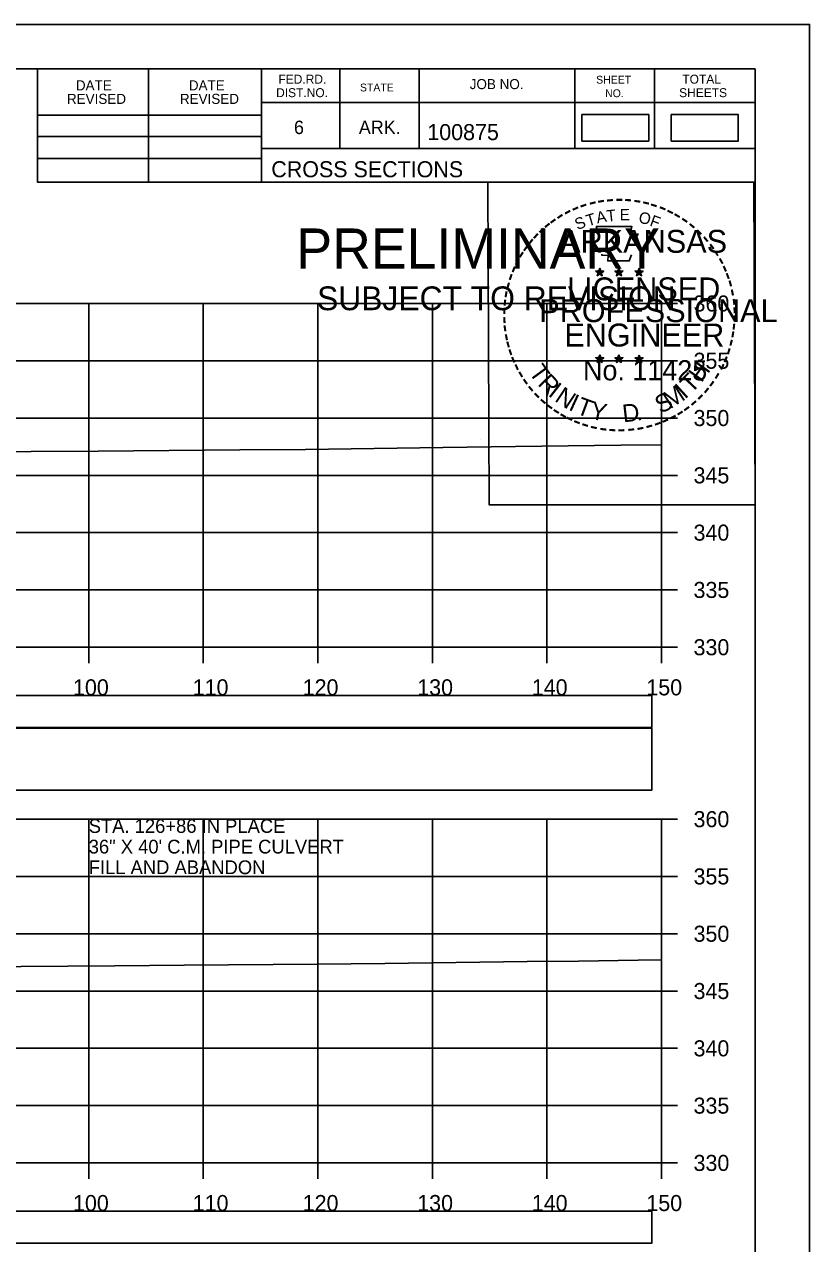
# Model space of a CAD drawing. Extents: x 1368122 to 1710785, y 373130 to 557566.
# Drawn here: x 1368783.3 to 1368851.8, y 376864 to 376970.4 of the extents above; entities that cross this region are included whole.
import ezdxf

# ---------------------------------------------------------------- set-up
doc = ezdxf.new("R2010")
doc.units = 0
for name, color, linetype in [('R_Alt Surface', 7, 'Continuous'), ('R_Axis', 7, 'Continuous'), ('R_Axis Annot', 7, 'Continuous'), ('R_Border', 7, 'Continuous'), ('R_Border PE', 7, 'Continuous'), ('R_Border Prem', 7, 'Continuous'), ('R_Drive', 7, 'Continuous'), ('R_Exist Surface', 7, 'Continuous'), ('R_Grid', 7, 'Continuous'), ('R_No Plot', 7, 'Continuous'), ('R_Water Annot', 7, 'Continuous')]:
    doc.layers.add(name, color=color, linetype=linetype)

msp = doc.modelspace()

# ---------------------------------------------------------------- linework, layer by layer
msp.add_lwpolyline([(1368539.73, 376903.58), (1368838.03, 376903.58), (1368838.03, 376908.99), (1368539.73, 376908.99)], close=True)
at = {"layer": 'R_Alt Surface'}
for points in [[(1368539.73, 376909.05), (1368838.03, 376909.05), (1368838.03, 376911.86), (1368539.73, 376911.86)], [(1368539.73, 376864.05), (1368838.03, 376864.05), (1368838.03, 376866.86), (1368539.73, 376866.86)]]:
    msp.add_lwpolyline(points, close=True, dxfattribs=at)
at = {"layer": 'R_Axis'}
for p, q in [((1368838.88, 376916.06), (1368838.88, 376946.06)), ((1368840.28, 376946.06), (1368838.88, 376946.06)), ((1368840.28, 376941.06), (1368838.88, 376941.06)), ((1368840.28, 376936.06), (1368838.88, 376936.06)), ((1368840.28, 376931.06), (1368838.88, 376931.06)), ((1368840.28, 376926.06), (1368838.88, 376926.06)), ((1368840.28, 376921.06), (1368838.88, 376921.06)), ((1368538.88, 376916.06), (1368838.88, 376916.06)), ((1368788.88, 376914.66), (1368788.88, 376916.06)), ((1368798.88, 376914.66), (1368798.88, 376916.06)), ((1368808.88, 376914.66), (1368808.88, 376916.06)), ((1368818.88, 376914.66), (1368818.88, 376916.06)), ((1368828.88, 376914.66), (1368828.88, 376916.06)), ((1368838.88, 376914.66), (1368838.88, 376916.06)), ((1368840.28, 376916.06), (1368838.88, 376916.06)), ((1368838.88, 376871.06), (1368838.88, 376901.06)), ((1368840.28, 376901.06), (1368838.88, 376901.06)), ((1368840.28, 376896.06), (1368838.88, 376896.06)), ((1368840.28, 376891.06), (1368838.88, 376891.06)), ((1368840.28, 376886.06), (1368838.88, 376886.06)), ((1368840.28, 376881.06), (1368838.88, 376881.06)), ((1368840.28, 376876.06), (1368838.88, 376876.06)), ((1368538.88, 376871.06), (1368838.88, 376871.06)), ((1368788.88, 376869.66), (1368788.88, 376871.06)), ((1368798.88, 376869.66), (1368798.88, 376871.06)), ((1368808.88, 376869.66), (1368808.88, 376871.06)), ((1368818.88, 376869.66), (1368818.88, 376871.06)), ((1368828.88, 376869.66), (1368828.88, 376871.06)), ((1368838.88, 376869.66), (1368838.88, 376871.06)), ((1368840.28, 376871.06), (1368838.88, 376871.06))]:
    msp.add_line(p, q, dxfattribs=at)
at = {"layer": 'R_Border'}
for p, q in [((1368530.88, 376966.52), (1368847.06, 376966.52)), ((1368784.42, 376956.64), (1368784.42, 376966.52)), ((1368794.1, 376956.64), (1368794.1, 376966.52)), ((1368803.96, 376966.52), (1368803.96, 376956.64)), ((1368810.8, 376966.52), (1368810.8, 376959.58)), ((1368817.74, 376966.52), (1368817.74, 376959.58)), ((1368831.32, 376966.52), (1368831.32, 376959.58)), ((1368838.26, 376966.52), (1368838.26, 376959.58)), ((1368847.06, 376761.06), (1368847.06, 376966.52)), ((1368847.06, 376963.58), (1368803.96, 376963.58)), ((1368847.06, 376963.6), (1368847.06, 376963.6)), ((1368784.42, 376962.5), (1368803.96, 376962.5)), ((1368784.42, 376960.64), (1368803.96, 376960.64)), ((1368847.06, 376959.58), (1368803.96, 376959.58)), ((1368806.92, 376959.58), (1368847.06, 376959.58)), ((1368784.42, 376958.7), (1368803.96, 376958.7)), ((1368847.06, 376956.64), (1368784.42, 376956.64))]:
    msp.add_line(p, q, dxfattribs=at)
at = {"layer": 'R_Border PE'}
for p, q in [((1368833.15, 376948.89), (1368833.49, 376948.78)), ((1368833.15, 376948.89), (1368833.4, 376948.85)), ((1368833.15, 376948.89), (1368833.38, 376948.77)), ((1368833.28, 376948.48), (1368833.49, 376948.78)), ((1368833.28, 376948.48), (1368833.4, 376948.73)), ((1368833.28, 376948.48), (1368833.49, 376948.7)), ((1368833.49, 376949.14), (1368833.45, 376948.89)), ((1368833.49, 376948.78), (1368833.49, 376949.14)), ((1368833.49, 376949.14), (1368833.54, 376948.89)), ((1368833.84, 376948.89), (1368833.49, 376948.78)), ((1368833.71, 376948.48), (1368833.49, 376948.78)), ((1368833.71, 376948.48), (1368833.49, 376948.7)), ((1368833.84, 376948.89), (1368833.56, 376948.84)), ((1368833.71, 376948.48), (1368833.57, 376948.77)), ((1368833.84, 376948.89), (1368833.64, 376948.79)), ((1368834.82, 376948.89), (1368835.16, 376948.78)), ((1368834.82, 376948.89), (1368835.07, 376948.85)), ((1368834.82, 376948.89), (1368835.05, 376948.77)), ((1368834.95, 376948.48), (1368835.16, 376948.78)), ((1368834.95, 376948.48), (1368835.07, 376948.73)), ((1368834.95, 376948.48), (1368835.16, 376948.7)), ((1368835.16, 376949.14), (1368835.12, 376948.89)), ((1368835.16, 376948.78), (1368835.16, 376949.14)), ((1368835.16, 376949.14), (1368835.21, 376948.89)), ((1368835.51, 376948.89), (1368835.16, 376948.78)), ((1368835.38, 376948.48), (1368835.16, 376948.78)), ((1368835.38, 376948.48), (1368835.16, 376948.7)), ((1368835.51, 376948.89), (1368835.23, 376948.84)), ((1368835.38, 376948.48), (1368835.24, 376948.77)), ((1368835.51, 376948.89), (1368835.31, 376948.79)), ((1368836.58, 376948.88), (1368836.93, 376948.77)), ((1368836.58, 376948.88), (1368836.83, 376948.83)), ((1368836.58, 376948.88), (1368836.82, 376948.76)), ((1368836.71, 376948.47), (1368836.93, 376948.77)), ((1368836.71, 376948.47), (1368836.84, 376948.71)), ((1368836.71, 376948.47), (1368836.93, 376948.69)), ((1368836.93, 376949.13), (1368836.89, 376948.88)), ((1368836.93, 376948.77), (1368836.93, 376949.13)), ((1368836.93, 376949.13), (1368836.98, 376948.88)), ((1368837.28, 376948.88), (1368836.93, 376948.77)), ((1368837.14, 376948.47), (1368836.93, 376948.77)), ((1368837.14, 376948.47), (1368836.93, 376948.68)), ((1368837.28, 376948.88), (1368836.99, 376948.83)), ((1368837.14, 376948.47), (1368837, 376948.76)), ((1368837.28, 376948.88), (1368837.07, 376948.78)), ((1368833.14, 376941.32), (1368833.49, 376941.21)), ((1368833.14, 376941.32), (1368833.39, 376941.27)), ((1368833.14, 376941.32), (1368833.38, 376941.2)), ((1368833.27, 376940.91), (1368833.49, 376941.21)), ((1368833.27, 376940.91), (1368833.4, 376941.15)), ((1368833.27, 376940.91), (1368833.49, 376941.13)), ((1368833.49, 376941.57), (1368833.45, 376941.32)), ((1368833.49, 376941.21), (1368833.49, 376941.57)), ((1368833.49, 376941.57), (1368833.54, 376941.32)), ((1368833.84, 376941.32), (1368833.49, 376941.21)), ((1368833.7, 376940.91), (1368833.49, 376941.21)), ((1368833.7, 376940.91), (1368833.49, 376941.12)), ((1368833.84, 376941.32), (1368833.55, 376941.27)), ((1368833.7, 376940.91), (1368833.57, 376941.2)), ((1368833.84, 376941.32), (1368833.63, 376941.22)), ((1368834.81, 376941.32), (1368835.16, 376941.21)), ((1368834.81, 376941.32), (1368835.06, 376941.27)), ((1368834.81, 376941.32), (1368835.05, 376941.2)), ((1368834.94, 376940.91), (1368835.16, 376941.21)), ((1368834.94, 376940.91), (1368835.07, 376941.15)), ((1368834.94, 376940.91), (1368835.16, 376941.13)), ((1368835.16, 376941.57), (1368835.12, 376941.32)), ((1368835.16, 376941.21), (1368835.16, 376941.57)), ((1368835.16, 376941.57), (1368835.21, 376941.32)), ((1368835.51, 376941.32), (1368835.16, 376941.21)), ((1368835.37, 376940.91), (1368835.16, 376941.21)), ((1368835.37, 376940.91), (1368835.16, 376941.12)), ((1368835.51, 376941.32), (1368835.22, 376941.27)), ((1368835.37, 376940.91), (1368835.24, 376941.2)), ((1368835.51, 376941.32), (1368835.3, 376941.22)), ((1368836.58, 376941.31), (1368836.93, 376941.2)), ((1368836.58, 376941.31), (1368836.83, 376941.26)), ((1368836.58, 376941.31), (1368836.81, 376941.19)), ((1368836.71, 376940.9), (1368836.93, 376941.2)), ((1368836.71, 376940.9), (1368836.84, 376941.14)), ((1368836.71, 376940.9), (1368836.92, 376941.12)), ((1368836.93, 376941.56), (1368836.89, 376941.31)), ((1368837.14, 376940.9), (1368836.92, 376941.11)), ((1368836.93, 376941.2), (1368836.93, 376941.56)), ((1368836.93, 376941.56), (1368836.98, 376941.31)), ((1368837.27, 376941.31), (1368836.93, 376941.2)), ((1368837.14, 376940.9), (1368836.93, 376941.2)), ((1368837.27, 376941.31), (1368836.99, 376941.26)), ((1368837.14, 376940.9), (1368837, 376941.19)), ((1368837.27, 376941.31), (1368837.07, 376941.21))]:
    msp.add_line(p, q, dxfattribs=at)
for points in [[(1368833.19, 376952.77), (1368833.46, 376951.94)], [(1368836.7, 376951.85), (1368836.84, 376952.13), (1368836.15, 376952.11), (1368836.3, 376952.77), (1368833.19, 376952.77)], [(1368833.68, 376950.35), (1368833.68, 376950.26), (1368834.24, 376950.24), (1368834.19, 376949.77), (1368836.06, 376949.77), (1368836.26, 376950.3)], [(1368833.49, 376949.14), (1368833.71, 376948.48), (1368833.15, 376948.89), (1368833.84, 376948.89), (1368833.28, 376948.48), (1368833.49, 376949.14)], [(1368835.16, 376949.14), (1368835.38, 376948.48), (1368834.82, 376948.89), (1368835.51, 376948.89), (1368834.95, 376948.48), (1368835.16, 376949.14)], [(1368836.93, 376949.13), (1368837.14, 376948.47), (1368836.58, 376948.88), (1368837.28, 376948.88), (1368836.71, 376948.47), (1368836.93, 376949.13)], [(1368833.49, 376941.57), (1368833.7, 376940.91), (1368833.14, 376941.32), (1368833.84, 376941.32), (1368833.27, 376940.91), (1368833.49, 376941.57)], [(1368835.16, 376941.57), (1368835.37, 376940.91), (1368834.81, 376941.32), (1368835.51, 376941.32), (1368834.94, 376940.91), (1368835.16, 376941.57)], [(1368836.93, 376941.56), (1368837.14, 376940.9), (1368836.58, 376941.31), (1368837.27, 376941.31), (1368836.71, 376940.9), (1368836.93, 376941.56)]]:
    msp.add_lwpolyline(points, dxfattribs=at)
for centre, radius in [((1368833.49, 376948.78), 0.172), ((1368833.49, 376948.78), 0.145), ((1368833.49, 376948.78), 0.116), ((1368833.49, 376948.78), 0.0991), ((1368833.49, 376948.78), 0.0747), ((1368833.49, 376948.78), 0.0495), ((1368833.49, 376948.78), 0.0296), ((1368835.16, 376948.78), 0.172), ((1368835.16, 376948.78), 0.145), ((1368835.16, 376948.78), 0.116), ((1368835.16, 376948.78), 0.0991), ((1368835.16, 376948.78), 0.0747), ((1368835.16, 376948.78), 0.0495), ((1368835.16, 376948.78), 0.0296), ((1368836.93, 376948.77), 0.172), ((1368836.93, 376948.77), 0.145), ((1368836.93, 376948.77), 0.116), ((1368836.93, 376948.77), 0.0991), ((1368836.93, 376948.77), 0.0747), ((1368836.93, 376948.77), 0.0495), ((1368836.93, 376948.77), 0.0296), ((1368833.49, 376941.21), 0.172), ((1368833.49, 376941.21), 0.145), ((1368833.49, 376941.21), 0.116), ((1368833.49, 376941.21), 0.0991), ((1368833.49, 376941.21), 0.0747), ((1368833.49, 376941.21), 0.0495), ((1368833.49, 376941.21), 0.0296), ((1368835.16, 376941.21), 0.172), ((1368835.16, 376941.21), 0.145), ((1368835.16, 376941.21), 0.116), ((1368835.16, 376941.21), 0.0991), ((1368835.16, 376941.21), 0.0747), ((1368835.16, 376941.21), 0.0495), ((1368835.16, 376941.21), 0.0296), ((1368836.93, 376941.2), 0.172), ((1368836.93, 376941.2), 0.145), ((1368836.93, 376941.2), 0.116), ((1368836.93, 376941.2), 0.0991), ((1368836.93, 376941.2), 0.0747), ((1368836.93, 376941.2), 0.0495), ((1368836.93, 376941.2), 0.0296)]:
    msp.add_circle(centre, radius, dxfattribs=at)
at = {"layer": 'R_Drive'}
for points in [[(1368831.93, 376960.23), (1368837.77, 376960.23), (1368837.77, 376962.54), (1368831.93, 376962.54)], [(1368839.74, 376960.23), (1368845.58, 376960.23), (1368845.58, 376962.54), (1368839.74, 376962.54)]]:
    msp.add_lwpolyline(points, close=True, dxfattribs=at)
at = {"layer": 'R_Exist Surface'}
for points in [[(1368729.58, 376932.49), (1368745.62, 376932.97), (1368749.59, 376932.96), (1368756.77, 376933.04), (1368771.96, 376933.08), (1368783.85, 376933.13), (1368789.71, 376933.18), (1368802.07, 376933.29), (1368807.81, 376933.32), (1368819.78, 376933.5), (1368826.13, 376933.58), (1368835.33, 376933.69), (1368838.88, 376933.73)], [(1368733.93, 376887.72), (1368745.81, 376888.08), (1368748.59, 376888.06), (1368752.7, 376888.08), (1368772.93, 376888.14), (1368778.86, 376888.17), (1368791.15, 376888.26), (1368797.21, 376888.31), (1368808.86, 376888.39), (1368814.72, 376888.47), (1368827.17, 376888.63), (1368831.64, 376888.68), (1368836.86, 376888.75), (1368838.88, 376888.78)]]:
    msp.add_lwpolyline(points, dxfattribs=at)
at = {"layer": 'R_Grid'}
for p, q in [((1368538.88, 376946.06), (1368838.88, 376946.06)), ((1368788.88, 376916.06), (1368788.88, 376946.06)), ((1368798.88, 376916.06), (1368798.88, 376946.06)), ((1368808.88, 376916.06), (1368808.88, 376946.06)), ((1368818.88, 376916.06), (1368818.88, 376946.06)), ((1368828.88, 376916.06), (1368828.88, 376946.06)), ((1368838.88, 376916.06), (1368838.88, 376946.06)), ((1368538.88, 376941.06), (1368838.88, 376941.06)), ((1368538.88, 376936.06), (1368838.88, 376936.06)), ((1368538.88, 376931.06), (1368838.88, 376931.06)), ((1368538.88, 376926.06), (1368838.88, 376926.06)), ((1368538.88, 376921.06), (1368838.88, 376921.06)), ((1368538.88, 376916.06), (1368838.88, 376916.06)), ((1368538.88, 376901.06), (1368838.88, 376901.06)), ((1368788.88, 376871.06), (1368788.88, 376901.06)), ((1368798.88, 376871.06), (1368798.88, 376901.06)), ((1368808.88, 376871.06), (1368808.88, 376901.06)), ((1368818.88, 376871.06), (1368818.88, 376901.06)), ((1368828.88, 376871.06), (1368828.88, 376901.06)), ((1368838.88, 376871.06), (1368838.88, 376901.06)), ((1368538.88, 376896.06), (1368838.88, 376896.06)), ((1368538.88, 376891.06), (1368838.88, 376891.06)), ((1368538.88, 376886.06), (1368838.88, 376886.06)), ((1368538.88, 376881.06), (1368838.88, 376881.06)), ((1368538.88, 376876.06), (1368838.88, 376876.06)), ((1368538.88, 376871.06), (1368838.88, 376871.06))]:
    msp.add_line(p, q, dxfattribs=at)
at = {"layer": 'R_No Plot'}
for p, q in [((1368518.48, 376970.41), (1368851.81, 376970.41)), ((1368823.09, 376934.18), (1368823.09, 376934.18))]:
    msp.add_line(p, q, dxfattribs=at)
for points in [[(1368518.47, 376970.41), (1368851.81, 376970.41), (1368851.81, 376757.07), (1368518.47, 376757.07)], [(1368764.8, 376966.52), (1368784.42, 376966.52), (1368784.42, 376956.64), (1368800.53, 376956.64), (1368823.73, 376956.64), (1368823.85, 376928.48), (1368847.06, 376928.48), (1368847.06, 376761.06), (1368530.88, 376761.06), (1368530.88, 376966.52)], [(1368823.73, 376956.64), (1368846.94, 376956.64), (1368847.06, 376928.48), (1368823.85, 376928.48)]]:
    msp.add_lwpolyline(points, close=True, dxfattribs=at)

# ---------------------------------------------------------------- texts
at = {"layer": 'R_Axis Annot'}
for s, p in [('360', (1368841.68, 376945.36)), ('355', (1368841.68, 376940.36)), ('350', (1368841.68, 376935.36)), ('345', (1368841.68, 376930.36)), ('340', (1368841.68, 376925.36)), ('335', (1368841.68, 376920.36)), ('330', (1368841.68, 376915.36)), ('100', (1368787.51, 376911.86)), ('110', (1368797.96, 376911.86)), ('120', (1368807.56, 376911.86)), ('130', (1368817.56, 376911.86)), ('140', (1368827.56, 376911.86)), ('150', (1368837.56, 376911.86)), ('360', (1368841.68, 376900.36)), ('355', (1368841.68, 376895.36)), ('350', (1368841.68, 376890.36)), ('345', (1368841.68, 376885.36)), ('340', (1368841.68, 376880.36)), ('335', (1368841.68, 376875.36)), ('330', (1368841.68, 376870.36)), ('100', (1368787.51, 376866.86)), ('110', (1368797.96, 376866.86)), ('120', (1368807.56, 376866.86)), ('130', (1368817.56, 376866.86)), ('140', (1368827.56, 376866.86)), ('150', (1368837.56, 376866.86))]:
    msp.add_text(s, height=1.4, dxfattribs=at).set_placement(p)
at = {"layer": 'R_Border'}
for s, height, p in [('DATE', 0.879, (1368787.76, 376964.65)), ('DATE', 0.879, (1368797.62, 376964.65)), ('FED.RD.', 0.782, (1368805.44, 376965.24)), ('JOB NO.', 0.879, (1368822.14, 376964.76)), ('SHEET', 0.684, (1368833.18, 376965.24)), ('TOTAL', 0.782, (1368840.7, 376965.24)), ('REVISED', 0.879, (1368786.98, 376963.47)), ('REVISED', 0.879, (1368796.84, 376963.47)), ('DIST.NO.', 0.782, (1368805.24, 376964.06)), ('STATE', 0.684, (1368812.56, 376964.56)), ('NO.', 0.684, (1368833.96, 376964.06)), ('SHEETS', 0.782, (1368840.42, 376964.06)), ('6', 1.17, (1368806.8, 376960.84)), ('ARK.', 1.172, (1368812.46, 376960.84)), ('100875', 1.4, (1368818.44, 376960.31)), ('CROSS SECTIONS', 1.4, (1368804.82, 376957.07))]:
    msp.add_text(s, height=height, rotation=360, dxfattribs=at).set_placement(p)
at = {"layer": 'R_Border PE'}
for s, height, rotation, p in [('-', 1.6, 19.1761, (1368831.93, 376953.9)), ('-', 1.6, 13.6301, (1368832.68, 376954.14)), ('-', 1.6, 10.2193, (1368833.36, 376954.3)), ('-', 1.6, 5.8968, (1368834.09, 376954.41)), ('-', 1.6, 0.1862, (1368834.86, 376954.48)), ('-', 1.6, 357.743, (1368835.59, 376954.47)), ('-', 1.6, 352.1617, (1368836.33, 376954.41)), ('-', 1.6, 347.2049, (1368837.05, 376954.3)), ('-', 1.6, 342.3362, (1368837.68, 376954.14)), ('-', 1.6, 34.0636, (1368830.07, 376952.94)), ('-', 1.6, 28.7918, (1368830.67, 376953.31)), ('-', 1.6, 24.3072, (1368831.3, 376953.63)), ('T', 1, 16.4036, (1368832.46, 376952.78)), ('A', 1, 11.2132, (1368833.28, 376953.03)), ('T', 1, 6.0228, (1368834.13, 376953.19)), ('E', 1, 0.8323, (1368835.24, 376953.3)), ('O', 1, 350.4515, (1368836.84, 376953.09)), ('F', 1, 340.0707, (1368837.79, 376952.87)), ('-', 1.6, 337.8551, (1368838.42, 376953.92)), ('-', 1.6, 334.1211, (1368839.05, 376953.65)), ('-', 1.6, 329.6409, (1368839.63, 376953.37)), ('-', 1.6, 42.9622, (1368828.58, 376951.75)), ('-', 1.6, 38.9507, (1368829.02, 376952.17)), ('-', 1.6, 36.2317, (1368829.49, 376952.54)), ('S', 1, 21.594, (1368831.54, 376952.45)), ('-', 1.6, 325.8627, (1368840.27, 376953)), ('-', 1.6, 320.5297, (1368840.88, 376952.58)), ('-', 1.6, 50.6142, (1368827.73, 376950.79)), ('-', 1.6, 48.423, (1368828.14, 376951.27)), ('ARKANSAS', 2, 360, (1368830.04, 376950.48)), ('-', 1.6, 315.5786, (1368841.48, 376952.09)), ('-', 1.6, 309.8797, (1368842.05, 376951.54)), ('-', 1.6, 58.0706, (1368826.99, 376949.69)), ('-', 1.6, 54.2325, (1368827.32, 376950.22)), ('-', 1.6, 306.6522, (1368842.58, 376950.94)), ('-', 1.4, 303.6753, (1368843.06, 376950.37)), ('-', 1.6, 62.8713, (1368826.68, 376949.08)), ('-', 1.6, 299.6684, (1368843.38, 376949.76)), ('-', 1.6, 72.3945, (1368826.2, 376947.84)), ('-', 1.6, 67.7743, (1368826.42, 376948.47)), ('LICENSED', 2, 360, (1368830.64, 376946.33)), ('DWB', 0.01, 360, (1368833.48, 376948.77)), ('DWB', 0.01, 360, (1368835.15, 376948.77)), ('DWB', 0.01, 360, (1368836.92, 376948.76)), ('-', 1.6, 294.6628, (1368843.7, 376949.15)), ('-', 1.6, 290.5728, (1368843.96, 376948.57)), ('-', 1.6, 75.461, (1368826.01, 376947.12)), ('-', 1.6, 285.1233, (1368844.2, 376947.99)), ('-', 1.6, 280.5493, (1368844.4, 376947.25)), ('-', 1.6, 85.1863, (1368825.8, 376945.72)), ('-', 1.6, 81.2013, (1368825.87, 376946.41)), ('PROFESSIONAL', 2, 360, (1368828.21, 376944.43)), ('-', 1.6, 276.5962, (1368844.56, 376946.48)), ('-', 1.6, 89.0622, (1368825.77, 376945.02)), ('-', 1.6, 274.3301, (1368844.62, 376945.76)), ('-', 1.6, 94.1959, (1368825.81, 376944.29)), ('-', 1.6, 98.9479, (1368825.88, 376943.63)), ('ENGINEER', 2, 360, (1368830.4, 376942.3)), ('-', 1.6, 263.5172, (1368844.63, 376944.46)), ('-', 1.6, 269.9407, (1368844.65, 376945.13)), ('-', 1.6, 101.7149, (1368826.02, 376942.89)), ('-', 1.6, 260.9953, (1368844.56, 376943.81)), ('-', 1.6, 105.4578, (1368826.18, 376942.3)), ('-', 1.6, 109.0874, (1368826.39, 376941.67)), ('-', 1.6, 252.8681, (1368844.27, 376942.41)), ('-', 1.6, 255.7626, (1368844.45, 376943.13)), ('-', 1.6, 114.0643, (1368826.65, 376941.07)), ('T', 1.54, 306.0406, (1368827.25, 376940.04)), ('No. 11425', 1.757, 360, (1368832.03, 376939.35)), ('DWB', 0.01, 360, (1368833.48, 376941.2)), ('DWB', 0.01, 360, (1368835.15, 376941.2)), ('DWB', 0.01, 360, (1368836.91, 376941.19)), ('H', 1.54, 54.6088, (1368842.37, 376939.08)), ('-', 1.6, 247.8887, (1368844.05, 376941.74)), ('-', 1.6, 115.7289, (1368826.95, 376940.45)), ('-', 1.6, 120.4471, (1368827.31, 376939.87)), ('R', 1.54, 314.005, (1368828.01, 376939)), ('T', 1.54, 46.6444, (1368841.48, 376938.14)), ('-', 1.6, 239.0712, (1368843.39, 376940.36)), ('-', 1.6, 244.6197, (1368843.79, 376941.11)), ('-', 1.6, 125.8934, (1368827.71, 376939.31)), ('-', 1.6, 130.7181, (1368828.17, 376938.75)), ('I', 1.54, 321.9694, (1368828.91, 376938.06)), ('N', 1.54, 326.5002, (1368829.48, 376937.59)), ('M', 1.54, 32.6563, (1368839.63, 376936.81)), ('I', 1.54, 42.1136, (1368840.92, 376937.66)), ('-', 1.6, 233.8452, (1368842.99, 376939.71)), ('-', 1.6, 134.2238, (1368828.69, 376938.21)), ('-', 1.6, 138.9338, (1368829.22, 376937.74)), ('I', 1.54, 335.3603, (1368830.69, 376936.81)), ('T', 1.54, 339.8912, (1368831.35, 376936.48)), ('S', 1.54, 26.9312, (1368838.8, 376936.41)), ('-', 1.6, 225.7653, (1368842.08, 376938.58)), ('-', 1.6, 231.2538, (1368842.56, 376939.14)), ('-', 1.6, 144.6463, (1368829.77, 376937.34)), ('-', 1.6, 148.0898, (1368830.33, 376936.97)), ('Y', 1.54, 347.8556, (1368832.57, 376936.03)), ('D', 1.54, 6.3969, (1368835.55, 376935.68)), ('-', 1.6, 212.2491, (1368840.48, 376937.21)), ('-', 1.6, 215.7363, (1368841.01, 376937.59)), ('-', 1.6, 221.0851, (1368841.56, 376938.07)), ('-', 1.6, 151.5704, (1368830.91, 376936.64)), ('-', 1.6, 154.6002, (1368831.43, 376936.4)), ('-', 1.6, 158.5612, (1368832.06, 376936.14)), ('-', 1.6, 162.7983, (1368832.74, 376935.93)), ('.', 1.54, 13.7642, (1368836.74, 376935.8)), ('-', 1.6, 200.7184, (1368838.67, 376936.27)), ('-', 1.6, 204.2516, (1368839.29, 376936.54)), ('-', 1.6, 207.3568, (1368839.92, 376936.86)), ('-', 1.6, 167.5555, (1368833.46, 376935.76)), ('-', 1.6, 173.1155, (1368834.23, 376935.65)), ('-', 1.6, 176.5183, (1368834.98, 376935.6)), ('-', 1.6, 181.5918, (1368835.72, 376935.62)), ('-', 1.6, 185.8167, (1368836.53, 376935.7)), ('-', 1.6, 191.2858, (1368837.27, 376935.83)), ('-', 1.6, 195.4743, (1368838, 376936.03))]:
    msp.add_text(s, height=height, rotation=rotation, dxfattribs=at).set_placement(p)
at = {"layer": 'R_Border Prem'}
for s, height, p in [('PRELIMINARY', 3.5, (1368807.01, 376949.1)), ('DWB', 0.01, (1368807.76, 376950.95)), ('SUBJECT TO REVISION', 2.0751, (1368808.82, 376945.47))]:
    msp.add_text(s, height=height, rotation=360, dxfattribs=at).set_placement(p)
at = {"layer": 'R_Water Annot'}
for s, p in [('STA. 126+86 IN PLACE', (1368788.88, 376899.86)), ('36" X 40\' C.M. PIPE CULVERT', (1368788.88, 376898.06)), ('FILL AND ABANDON', (1368788.88, 376896.26))]:
    msp.add_text(s, height=1.2, dxfattribs=at).set_placement(p)

doc.saveas('drawing.dxf')
